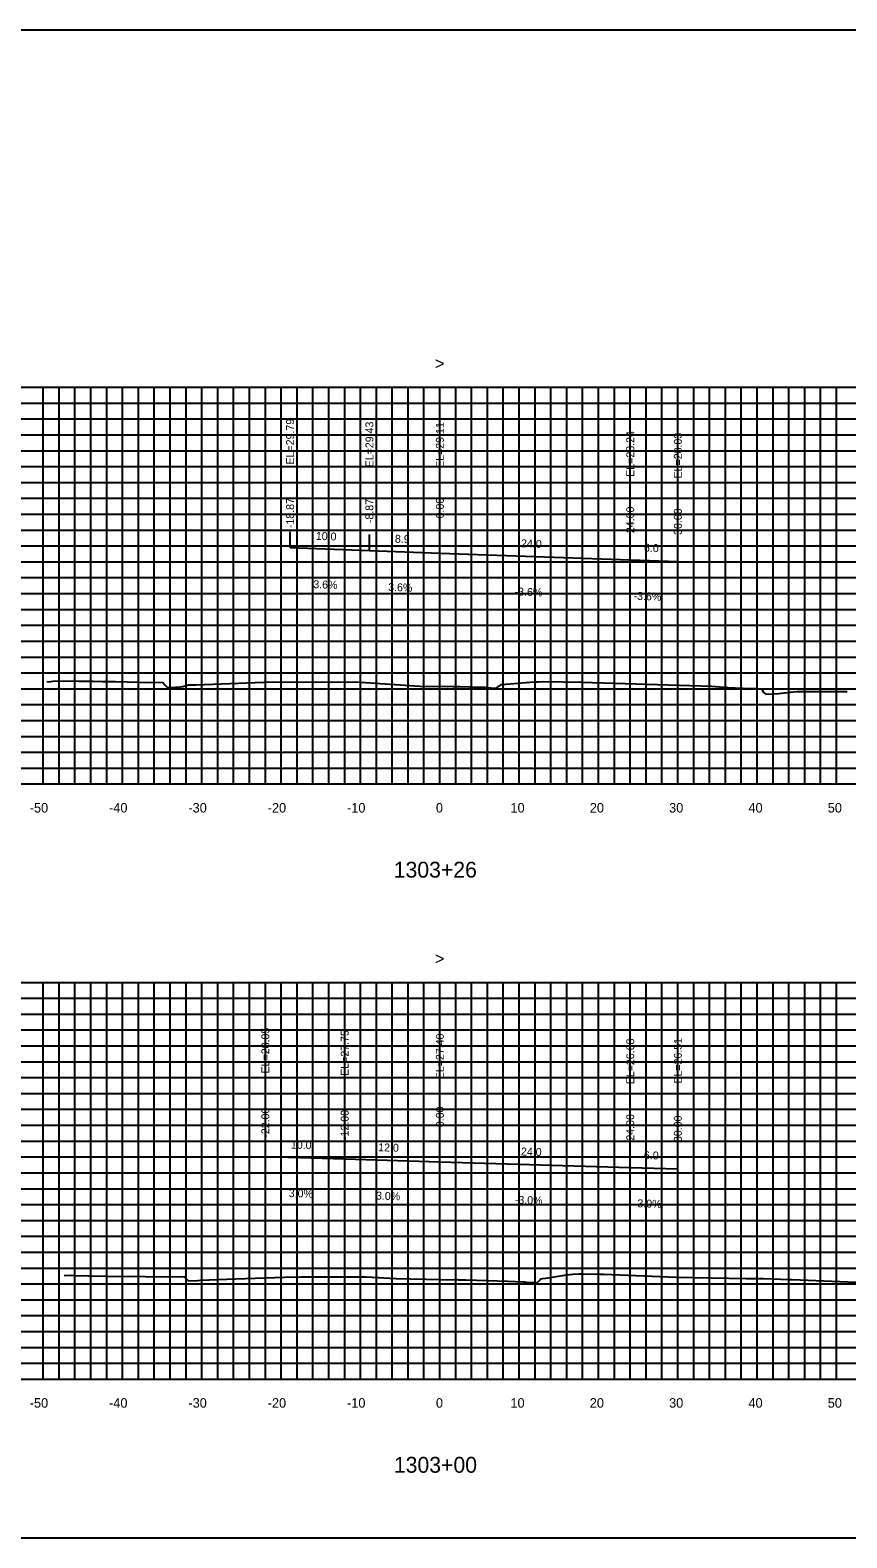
# Model space of a CAD drawing. Extents: x 1797714 to 1804825, y 249015 to 250269.
# Drawn here: x 1803232.5 to 1803335.5, y 249628.2 to 249818.2 of the extents above; entities that cross this region are included whole.
import ezdxf

# ---------------------------------------------------------------- set-up
doc = ezdxf.new("R2010")
doc.units = 0
for name, color, linetype in [('1', 7, 'Continuous'), ('10', 7, 'Continuous'), ('3', 7, 'Continuous'), ('4', 7, 'Continuous'), ('60', 7, 'Continuous'), ('CL-CNST', 7, 'Continuous'), ('Level 62', 7, 'Continuous'), ('M-ROADS', 7, 'Continuous')]:
    doc.layers.add(name, color=color, linetype=linetype)

msp = doc.modelspace()

# ---------------------------------------------------------------- linework, layer by layer
for p, q in [((1803265.28, 249752.95), (1803265.28, 249754.95)), ((1803275.28, 249752.59), (1803275.28, 249754.59)), ((1803284.16, 249752.27), (1803284.16, 249754.27)), ((1803308.16, 249751.41), (1803308.16, 249753.41)), ((1803314.16, 249751.19), (1803314.16, 249753.19)), ((1803262.16, 249676.21), (1803262.16, 249678.21)), ((1803272.16, 249675.92), (1803272.16, 249677.92)), ((1803284.16, 249675.56), (1803284.16, 249677.56)), ((1803308.16, 249674.85), (1803308.16, 249676.85)), ((1803314.16, 249674.67), (1803314.16, 249676.67))]:
    msp.add_line(p, q)
msp.add_lwpolyline([(1803134.16, 249628.17), (1803434.16, 249628.17), (1803434.16, 249818.17), (1803134.16, 249818.17)], close=True)
at = {"layer": '60'}
for p, q in [((1803134.16, 249723.17), (1803434.16, 249723.17)), ((1803234.16, 249723.11), (1803234.16, 249723.17)), ((1803244.16, 249723.11), (1803244.16, 249723.17)), ((1803254.16, 249723.11), (1803254.16, 249723.17)), ((1803264.16, 249723.11), (1803264.16, 249723.17)), ((1803274.16, 249723.11), (1803274.16, 249723.17)), ((1803284.16, 249723.11), (1803284.16, 249723.17)), ((1803294.16, 249723.11), (1803294.16, 249723.17)), ((1803304.16, 249723.11), (1803304.16, 249723.17)), ((1803314.16, 249723.11), (1803314.16, 249723.17)), ((1803324.16, 249723.11), (1803324.16, 249723.17)), ((1803334.16, 249723.11), (1803334.16, 249723.17)), ((1803134.16, 249648.17), (1803434.16, 249648.17)), ((1803234.16, 249648.11), (1803234.16, 249648.17)), ((1803244.16, 249648.11), (1803244.16, 249648.17)), ((1803254.16, 249648.11), (1803254.16, 249648.17)), ((1803264.16, 249648.11), (1803264.16, 249648.17)), ((1803274.16, 249648.11), (1803274.16, 249648.17)), ((1803284.16, 249648.11), (1803284.16, 249648.17)), ((1803294.16, 249648.11), (1803294.16, 249648.17)), ((1803304.16, 249648.11), (1803304.16, 249648.17)), ((1803314.16, 249648.11), (1803314.16, 249648.17)), ((1803324.16, 249648.11), (1803324.16, 249648.17)), ((1803334.16, 249648.11), (1803334.16, 249648.17))]:
    msp.add_line(p, q, dxfattribs=at)
at = {"layer": 'CL-CNST'}
for points in [[(1803265.28, 249752.95), (1803275.28, 249752.59), (1803284.16, 249752.27), (1803308.16, 249751.41), (1803314.16, 249751.19)], [(1803262.16, 249676.21), (1803272.16, 249675.92), (1803284.16, 249675.56), (1803308.16, 249674.85), (1803314.16, 249674.67)]]:
    msp.add_lwpolyline(points, dxfattribs=at)
at = {"layer": 'Level 62'}
for p, q in [((1803134.16, 249773.17), (1803434.16, 249773.17)), ((1803234.16, 249723.17), (1803234.16, 249773.17)), ((1803236.16, 249723.17), (1803236.16, 249773.17)), ((1803238.16, 249723.17), (1803238.16, 249773.17)), ((1803240.16, 249723.17), (1803240.16, 249773.17)), ((1803242.16, 249723.17), (1803242.16, 249773.17)), ((1803244.16, 249723.17), (1803244.16, 249773.17)), ((1803246.16, 249723.17), (1803246.16, 249773.17)), ((1803248.16, 249723.17), (1803248.16, 249773.17)), ((1803250.16, 249723.17), (1803250.16, 249773.17)), ((1803252.16, 249723.17), (1803252.16, 249773.17)), ((1803254.16, 249723.17), (1803254.16, 249773.17)), ((1803256.16, 249723.17), (1803256.16, 249773.17)), ((1803258.16, 249723.17), (1803258.16, 249773.17)), ((1803260.16, 249723.17), (1803260.16, 249773.17)), ((1803262.16, 249723.17), (1803262.16, 249773.17)), ((1803264.16, 249723.17), (1803264.16, 249773.17)), ((1803266.16, 249723.17), (1803266.16, 249773.17)), ((1803268.16, 249723.17), (1803268.16, 249773.17)), ((1803270.16, 249723.17), (1803270.16, 249773.17)), ((1803272.16, 249723.17), (1803272.16, 249773.17)), ((1803274.16, 249723.17), (1803274.16, 249773.17)), ((1803276.16, 249723.17), (1803276.16, 249773.17)), ((1803278.16, 249723.17), (1803278.16, 249773.17)), ((1803280.16, 249723.17), (1803280.16, 249773.17)), ((1803282.16, 249723.17), (1803282.16, 249773.17)), ((1803284.16, 249723.17), (1803284.16, 249773.17)), ((1803286.16, 249723.17), (1803286.16, 249773.17)), ((1803288.16, 249723.17), (1803288.16, 249773.17)), ((1803290.16, 249723.17), (1803290.16, 249773.17)), ((1803292.16, 249723.17), (1803292.16, 249773.17)), ((1803294.16, 249723.17), (1803294.16, 249773.17)), ((1803296.16, 249723.17), (1803296.16, 249773.17)), ((1803298.16, 249723.17), (1803298.16, 249773.17)), ((1803300.16, 249723.17), (1803300.16, 249773.17)), ((1803302.16, 249723.17), (1803302.16, 249773.17)), ((1803304.16, 249723.17), (1803304.16, 249773.17)), ((1803306.16, 249723.17), (1803306.16, 249773.17)), ((1803308.16, 249723.17), (1803308.16, 249773.17)), ((1803310.16, 249723.17), (1803310.16, 249773.17)), ((1803312.16, 249723.17), (1803312.16, 249773.17)), ((1803314.16, 249723.17), (1803314.16, 249773.17)), ((1803316.16, 249723.17), (1803316.16, 249773.17)), ((1803318.16, 249723.17), (1803318.16, 249773.17)), ((1803320.16, 249723.17), (1803320.16, 249773.17)), ((1803322.16, 249723.17), (1803322.16, 249773.17)), ((1803324.16, 249723.17), (1803324.16, 249773.17)), ((1803326.16, 249723.17), (1803326.16, 249773.17)), ((1803328.16, 249723.17), (1803328.16, 249773.17)), ((1803330.16, 249723.17), (1803330.16, 249773.17)), ((1803332.16, 249723.17), (1803332.16, 249773.17)), ((1803334.16, 249723.17), (1803334.16, 249773.17)), ((1803134.16, 249771.17), (1803434.16, 249771.17)), ((1803134.16, 249769.17), (1803434.16, 249769.17)), ((1803134.16, 249767.17), (1803434.16, 249767.17)), ((1803134.16, 249765.17), (1803434.16, 249765.17)), ((1803134.16, 249763.17), (1803434.16, 249763.17)), ((1803134.16, 249761.17), (1803434.16, 249761.17)), ((1803134.16, 249759.17), (1803434.16, 249759.17)), ((1803134.16, 249757.17), (1803434.16, 249757.17)), ((1803134.16, 249755.17), (1803434.16, 249755.17)), ((1803134.16, 249753.17), (1803434.16, 249753.17)), ((1803134.16, 249751.17), (1803434.16, 249751.17)), ((1803134.16, 249749.17), (1803434.16, 249749.17)), ((1803134.16, 249747.17), (1803434.16, 249747.17)), ((1803134.16, 249745.17), (1803434.16, 249745.17)), ((1803134.16, 249743.17), (1803434.16, 249743.17)), ((1803134.16, 249741.17), (1803434.16, 249741.17)), ((1803134.16, 249739.17), (1803434.16, 249739.17)), ((1803134.16, 249737.17), (1803434.16, 249737.17)), ((1803134.16, 249735.17), (1803434.16, 249735.17)), ((1803134.16, 249733.17), (1803434.16, 249733.17)), ((1803134.16, 249731.17), (1803434.16, 249731.17)), ((1803134.16, 249729.17), (1803434.16, 249729.17)), ((1803134.16, 249727.17), (1803434.16, 249727.17)), ((1803134.16, 249725.17), (1803434.16, 249725.17)), ((1803134.16, 249723.17), (1803434.16, 249723.17)), ((1803134.16, 249698.17), (1803434.16, 249698.17)), ((1803234.16, 249648.17), (1803234.16, 249698.17)), ((1803236.16, 249648.17), (1803236.16, 249698.17)), ((1803238.16, 249648.17), (1803238.16, 249698.17)), ((1803240.16, 249648.17), (1803240.16, 249698.17)), ((1803242.16, 249648.17), (1803242.16, 249698.17)), ((1803244.16, 249648.17), (1803244.16, 249698.17)), ((1803246.16, 249648.17), (1803246.16, 249698.17)), ((1803248.16, 249648.17), (1803248.16, 249698.17)), ((1803250.16, 249648.17), (1803250.16, 249698.17)), ((1803252.16, 249648.17), (1803252.16, 249698.17)), ((1803254.16, 249648.17), (1803254.16, 249698.17)), ((1803256.16, 249648.17), (1803256.16, 249698.17)), ((1803258.16, 249648.17), (1803258.16, 249698.17)), ((1803260.16, 249648.17), (1803260.16, 249698.17)), ((1803262.16, 249648.17), (1803262.16, 249698.17)), ((1803264.16, 249648.17), (1803264.16, 249698.17)), ((1803266.16, 249648.17), (1803266.16, 249698.17)), ((1803268.16, 249648.17), (1803268.16, 249698.17)), ((1803270.16, 249648.17), (1803270.16, 249698.17)), ((1803272.16, 249648.17), (1803272.16, 249698.17)), ((1803274.16, 249648.17), (1803274.16, 249698.17)), ((1803276.16, 249648.17), (1803276.16, 249698.17)), ((1803278.16, 249648.17), (1803278.16, 249698.17)), ((1803280.16, 249648.17), (1803280.16, 249698.17)), ((1803282.16, 249648.17), (1803282.16, 249698.17)), ((1803284.16, 249648.17), (1803284.16, 249698.17)), ((1803286.16, 249648.17), (1803286.16, 249698.17)), ((1803288.16, 249648.17), (1803288.16, 249698.17)), ((1803290.16, 249648.17), (1803290.16, 249698.17)), ((1803292.16, 249648.17), (1803292.16, 249698.17)), ((1803294.16, 249648.17), (1803294.16, 249698.17)), ((1803296.16, 249648.17), (1803296.16, 249698.17)), ((1803298.16, 249648.17), (1803298.16, 249698.17)), ((1803300.16, 249648.17), (1803300.16, 249698.17)), ((1803302.16, 249648.17), (1803302.16, 249698.17)), ((1803304.16, 249648.17), (1803304.16, 249698.17)), ((1803306.16, 249648.17), (1803306.16, 249698.17)), ((1803308.16, 249648.17), (1803308.16, 249698.17)), ((1803310.16, 249648.17), (1803310.16, 249698.17)), ((1803312.16, 249648.17), (1803312.16, 249698.17)), ((1803314.16, 249648.17), (1803314.16, 249698.17)), ((1803316.16, 249648.17), (1803316.16, 249698.17)), ((1803318.16, 249648.17), (1803318.16, 249698.17)), ((1803320.16, 249648.17), (1803320.16, 249698.17)), ((1803322.16, 249648.17), (1803322.16, 249698.17)), ((1803324.16, 249648.17), (1803324.16, 249698.17)), ((1803326.16, 249648.17), (1803326.16, 249698.17)), ((1803328.16, 249648.17), (1803328.16, 249698.17)), ((1803330.16, 249648.17), (1803330.16, 249698.17)), ((1803332.16, 249648.17), (1803332.16, 249698.17)), ((1803334.16, 249648.17), (1803334.16, 249698.17)), ((1803134.16, 249696.17), (1803434.16, 249696.17)), ((1803134.16, 249694.17), (1803434.16, 249694.17)), ((1803134.16, 249692.17), (1803434.16, 249692.17)), ((1803134.16, 249690.17), (1803434.16, 249690.17)), ((1803134.16, 249688.17), (1803434.16, 249688.17)), ((1803134.16, 249686.17), (1803434.16, 249686.17)), ((1803134.16, 249684.17), (1803434.16, 249684.17)), ((1803134.16, 249682.17), (1803434.16, 249682.17)), ((1803134.16, 249680.17), (1803434.16, 249680.17)), ((1803134.16, 249678.17), (1803434.16, 249678.17)), ((1803134.16, 249676.17), (1803434.16, 249676.17)), ((1803134.16, 249674.17), (1803434.16, 249674.17)), ((1803134.16, 249672.17), (1803434.16, 249672.17)), ((1803134.16, 249670.17), (1803434.16, 249670.17)), ((1803134.16, 249668.17), (1803434.16, 249668.17)), ((1803134.16, 249666.17), (1803434.16, 249666.17)), ((1803134.16, 249664.17), (1803434.16, 249664.17)), ((1803134.16, 249662.17), (1803434.16, 249662.17)), ((1803134.16, 249660.17), (1803434.16, 249660.17)), ((1803134.16, 249658.17), (1803434.16, 249658.17)), ((1803134.16, 249656.17), (1803434.16, 249656.17)), ((1803134.16, 249654.17), (1803434.16, 249654.17)), ((1803134.16, 249652.17), (1803434.16, 249652.17)), ((1803134.16, 249650.17), (1803434.16, 249650.17)), ((1803134.16, 249648.17), (1803434.16, 249648.17))]:
    msp.add_line(p, q, dxfattribs=at)
at = {"layer": 'M-ROADS'}
for points in [[(1803234.62, 249736.1), (1803234.86, 249736.06), (1803235.36, 249736.11), (1803237.45, 249736.16), (1803238.69, 249736.14), (1803239.26, 249736.13), (1803240.46, 249736.11), (1803241.6, 249736.1), (1803243.27, 249736.07), (1803246.24, 249736.01), (1803249.23, 249735.94), (1803249.54, 249735.61), (1803249.83, 249735.34), (1803250.77, 249735.38), (1803251.44, 249735.42), (1803251.75, 249735.45), (1803252.48, 249735.65), (1803253.44, 249735.68), (1803263, 249736.03), (1803266.94, 249736.01), (1803273.51, 249736.03), (1803281.63, 249735.51), (1803285.09, 249735.45), (1803285.44, 249735.48), (1803285.85, 249735.47), (1803286.65, 249735.45), (1803287.92, 249735.41), (1803289.04, 249735.38), (1803289.75, 249735.37), (1803289.87, 249735.37), (1803290.98, 249735.25), (1803291.26, 249735.23), (1803291.39, 249735.33), (1803291.95, 249735.71), (1803295.54, 249735.98), (1803296.05, 249736.04), (1803296.14, 249736.04), (1803296.55, 249736.04), (1803297.22, 249736.07), (1803302.04, 249735.99), (1803318.39, 249735.48), (1803320.42, 249735.34), (1803320.47, 249735.34), (1803323.3, 249735.22), (1803323.8, 249735.22), (1803324.21, 249735.22), (1803324.74, 249735.1), (1803324.92, 249734.73), (1803325.24, 249734.5), (1803326.9, 249734.58), (1803328.33, 249734.74), (1803329.21, 249734.84), (1803332.4, 249734.84), (1803332.61, 249734.84), (1803335.49, 249734.83)], [(1803236.8, 249661.21), (1803237.75, 249661.25), (1803238.03, 249661.22), (1803239.87, 249661.18), (1803239.88, 249661.2), (1803242.15, 249661.15), (1803251.95, 249661.06), (1803252.03, 249660.96), (1803252.47, 249660.55), (1803253.63, 249660.61), (1803253.94, 249660.63), (1803258.45, 249660.81), (1803264.57, 249661.02), (1803266.62, 249661.04), (1803274.86, 249661.07), (1803278.6, 249660.83), (1803286.18, 249660.69), (1803286.34, 249660.71), (1803286.52, 249660.7), (1803286.88, 249660.69), (1803287.46, 249660.68), (1803292.67, 249660.53), (1803294.7, 249660.42), (1803294.81, 249660.42), (1803295.01, 249660.4), (1803295.07, 249660.39), (1803295.69, 249660.35), (1803295.82, 249660.35), (1803296.19, 249660.35), (1803296.2, 249660.35), (1803296.25, 249660.35), (1803296.32, 249660.3), (1803296.37, 249660.31), (1803296.76, 249660.63), (1803296.78, 249660.63), (1803296.82, 249660.67), (1803296.88, 249660.76), (1803296.88, 249660.79), (1803297.1, 249660.83), (1803297.5, 249660.9), (1803300.12, 249661.31), (1803300.93, 249661.41), (1803301.66, 249661.43), (1803301.76, 249661.43), (1803302.17, 249661.43), (1803304.34, 249661.41), (1803304.84, 249661.39), (1803313.94, 249661.03), (1803322.76, 249660.86), (1803323.26, 249660.85), (1803323.9, 249660.84), (1803323.96, 249660.84), (1803324.45, 249660.84), (1803324.54, 249660.84), (1803324.9, 249660.84), (1803328.23, 249660.74), (1803328.58, 249660.73), (1803340.59, 249660.23)]]:
    msp.add_lwpolyline(points, dxfattribs=at)

# ---------------------------------------------------------------- texts
at = {"layer": '1'}
for s, p in [('1303+26', (1803278.34, 249711.37)), ('1303+00', (1803278.36, 249636.37))]:
    msp.add_text(s, height=2, dxfattribs=at).set_placement(p)
at = {"layer": '10'}
for s, p in [('-50', (1803232.46, 249719.57)), ('-40', (1803242.46, 249719.57)), ('-30', (1803252.46, 249719.57)), ('-20', (1803262.46, 249719.57)), ('-10', (1803272.46, 249719.57)), ('0', (1803283.66, 249719.57)), ('10', (1803293.06, 249719.57)), ('20', (1803303.06, 249719.57)), ('30', (1803313.06, 249719.57)), ('40', (1803323.06, 249719.57)), ('50', (1803333.06, 249719.57)), ('-50', (1803232.46, 249644.57)), ('-40', (1803242.46, 249644.57)), ('-30', (1803252.46, 249644.57)), ('-20', (1803262.46, 249644.57)), ('-10', (1803272.46, 249644.57)), ('0', (1803283.66, 249644.57)), ('10', (1803293.06, 249644.57)), ('20', (1803303.06, 249644.57)), ('30', (1803313.06, 249644.57)), ('40', (1803323.06, 249644.57)), ('50', (1803333.06, 249644.57))]:
    msp.add_text(s, height=1.2, dxfattribs=at).set_placement(p)
at = {"layer": '3'}
for s, p in [('EL=29.79', (1803265.78, 249763.43)), ('EL=29.43', (1803275.78, 249763.07)), ('EL=29.11', (1803284.66, 249763)), ('EL=28.24', (1803308.66, 249761.88)), ('EL=28.03', (1803314.66, 249761.67)), ('-18.87', (1803265.78, 249755.41)), ('-8.87', (1803275.78, 249756.04)), ('0.00', (1803284.66, 249756.64)), ('24.00', (1803308.66, 249754.78)), ('30.00', (1803314.66, 249754.56)), ('EL=28.05', (1803262.66, 249686.69)), ('EL=27.75', (1803272.66, 249686.39)), ('EL=27.40', (1803284.66, 249685.96)), ('EL=26.68', (1803308.66, 249685.32)), ('EL=26.51', (1803314.66, 249685.4)), ('-22.00', (1803262.66, 249678.59)), ('-12.00', (1803272.66, 249678.3)), ('0.00', (1803284.66, 249679.92)), ('24.00', (1803308.66, 249678.22)), ('30.00', (1803314.66, 249678.04))]:
    msp.add_text(s, height=1, rotation=90, dxfattribs=at).set_placement(p)
at = {"layer": '4'}
for s, rotation, p in [('10.0', 357.9382, (1803268.51, 249753.94)), ('8.9', 357.9382, (1803278.48, 249753.58)), ('24.0', 357.9382, (1803294.38, 249753.01)), ('6.0', 357.9382, (1803309.88, 249752.45)), ('3.6%', 357.9382, (1803268.19, 249747.85)), ('3.6%', 357.9382, (1803277.63, 249747.51)), ('-3.6%', 357.9382, (1803293.57, 249746.93)), ('-3.6%', 357.9382, (1803308.57, 249746.39)), ('10.0', 358.3037, (1803265.37, 249677.22)), ('12.0', 358.3037, (1803276.37, 249676.89)), ('24.0', 358.3037, (1803294.37, 249676.36)), ('6.0', 358.3037, (1803309.87, 249675.9)), ('3.0%', 358.3037, (1803265.1, 249671.12)), ('3.0%', 358.3037, (1803276.1, 249670.8)), ('-3.0%', 358.3037, (1803293.6, 249670.28)), ('-3.0%', 358.3037, (1803308.6, 249669.84))]:
    msp.add_text(s, height=1, rotation=rotation, dxfattribs=at).set_placement(p)
at = {"layer": '60'}
for p in [(1803283.55, 249775.42), (1803283.55, 249700.42)]:
    msp.add_text('>', height=1.5, dxfattribs=at).set_placement(p)

doc.saveas('drawing.dxf')
